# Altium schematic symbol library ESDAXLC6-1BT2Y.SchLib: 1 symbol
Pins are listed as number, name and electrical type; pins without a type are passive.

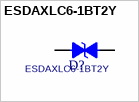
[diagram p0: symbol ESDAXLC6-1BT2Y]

## ESDAXLC6-1BT2Y
designator D?
footprint ST_SOD882TB
pins: 1, 2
